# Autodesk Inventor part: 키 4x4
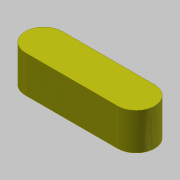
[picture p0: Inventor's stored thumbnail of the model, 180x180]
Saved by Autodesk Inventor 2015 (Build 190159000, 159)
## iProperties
Created: 2018-09
Part Number: 키 4x4
Document SubType Name: Modeling
Density: 7.86 g/cm^3
Material: 강철, 연강
Appearance: 노란색
Mass: 1.65269 g
Surface Area: 2.35398 cm^2
Volume: 0.210265 cm^3
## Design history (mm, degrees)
sketch "스케치1"
  geometry: L1 (-5, -2)-(5, -2); L2 (5, 2)-(-5, 2); A1 r 2 centre (5, 0) between (5, -2) and (5, 2); A2 r 2 centre (-5, 0) between (-5, 2) and (-5, -2); 2 further points
  constraints: 4 end point, 4 point on circle, 4 tangent, 2 centre point, 1 horizontal, 1 horizontal alignment, 1 midpoint, 1 parallel, 1 vertical alignment
  dimensions: "d0" = 4 distance between parallel lines of L1 L2; "d1" = 14 dimension on A1 A2
extrude "돌출1" new body sketch "스케치1" stored distance "d2" = 4; taper "d3" = 0 deg
node "솔리드1"
